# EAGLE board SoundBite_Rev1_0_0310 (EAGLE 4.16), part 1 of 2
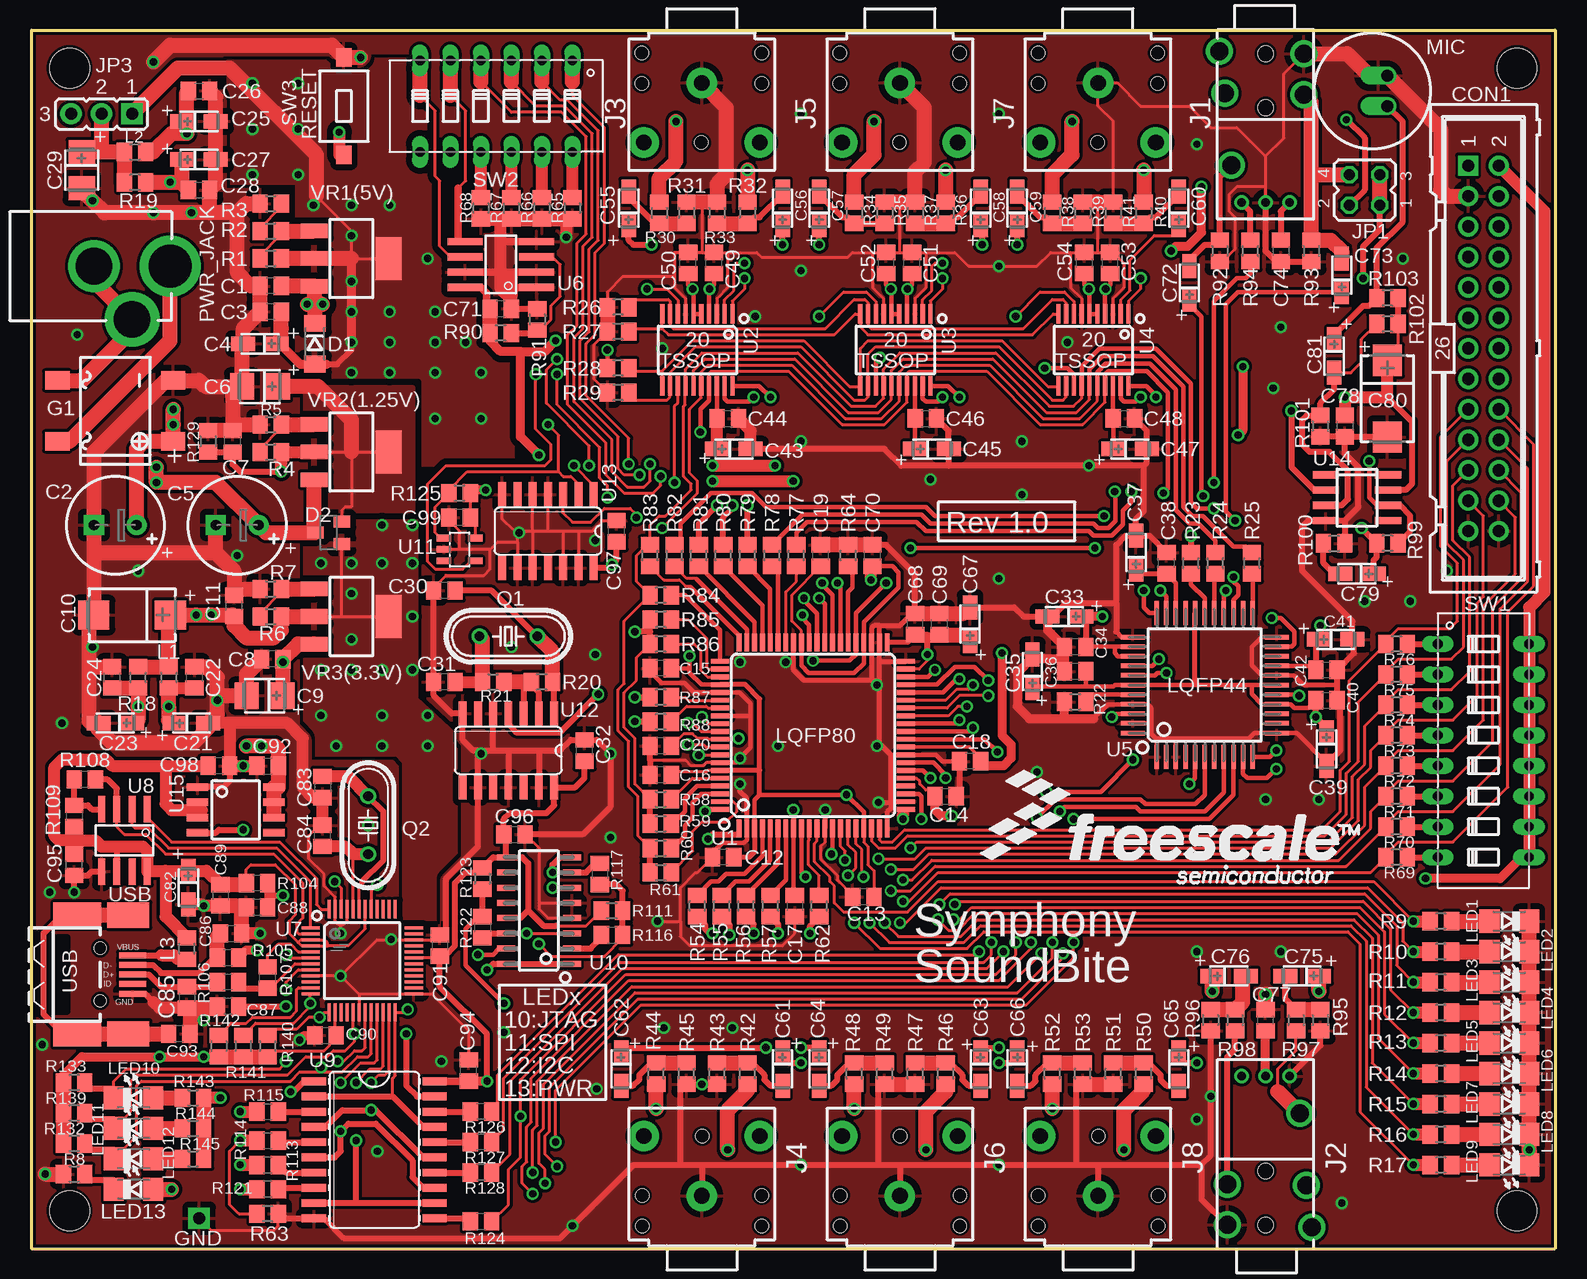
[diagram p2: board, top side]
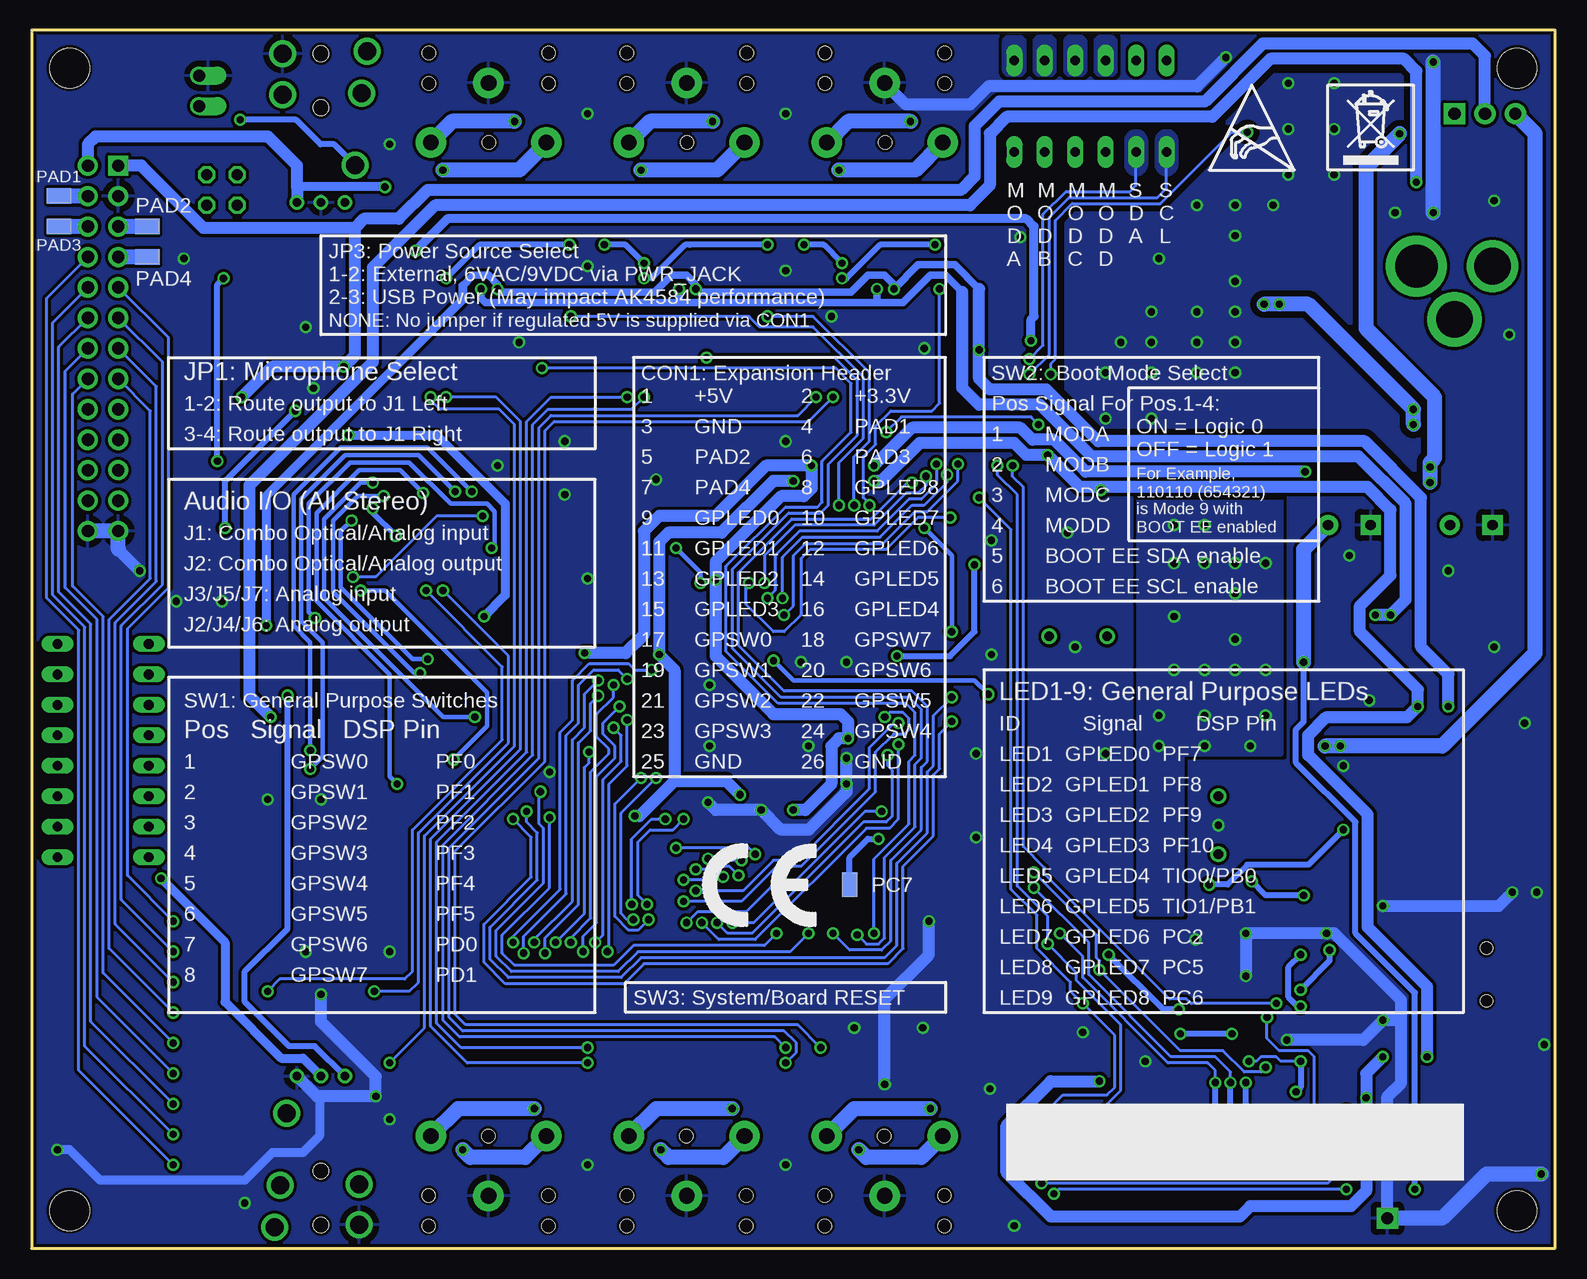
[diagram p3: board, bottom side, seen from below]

Size 127 x 101.6 mm. Coordinates in mm from the lower left corner, seen from the top.
Outline: 0,0 0,101.6 127,101.6 127,0 0,0
Copper layers (1*16): Top 0.035mm / dielectric 1.5mm / Bottom 0.035mm
Design rules "default": minimum track width 10mil, minimum drill 23.5mil, track to track 9.5mil, track to pad 9.5mil, pad to pad 9.5mil, via to via 9.5mil, smd to smd 0mil, copper to edge 10mil, drill to drill 8mil, minimum pad ring 10mil, minimum via ring 8mil, stop-mask expansion 4mil, vias tented up to drill 24mil, thermal gap 20mil
Net classes: 0 default: width 0.076 mm; 1 pwr: width 0.254 mm
Holes 3.3 mm at 3.17,98.42 123.83,98.42 123.83,3.17 3.17,3.17

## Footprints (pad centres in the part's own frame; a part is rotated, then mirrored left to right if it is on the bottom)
C0805_5MIL = smd 1.27 x 1.524: 1 -0.889,0; 2 0.889,0
E3,5-8 = drill 0.864 pad 1.676 round: + -1.778,0 | drill 0.864 pad 1.676 square: - 1.778,0
CT3216 = smd 2 x 1.2: + -1.4,0; - 1.4,0
CT3528 = smd 2 x 2.2: + -1.5,0; - 1.5,0
CT7343 = smd 2.6 x 2.4: + -3.2,0; - 3.2,0
0805 = smd 1.27 x 1.524: P$1 -0.889,0; P$2 0.889,0
ML26 = drill 1.016 pad 1.676 square: 1 -15.24,-1.27 | drill 1.016 pad 1.676 round: 2 -15.24,1.27; 3 -12.7,-1.27; 4 -12.7,1.27; 5 -10.16,-1.27; 6 -10.16,1.27; 7 -7.62,-1.27; 8 -7.62,1.27; 9 -5.08,-1.27; 10 -5.08,1.27; 11 -2.54,-1.27; 12 -2.54,1.27; 13 0,-1.27; 14 0,1.27; 15 2.54,-1.27; 16 2.54,1.27; 17 5.08,-1.27; 18 5.08,1.27; 19 7.62,-1.27; 20 7.62,1.27; 21 10.16,-1.27; 22 10.16,1.27; 23 12.7,-1.27; 24 12.7,1.27; 25 15.24,-1.27; 26 15.24,1.27
SOD80 = smd 1.4 x 1.8: 1 -1.7,0; 2 1.7,0
SOT23C = smd 1 x 1.4: 1 -0.95,-1.1; 2 0.95,-1.1; 3 0,1.1
DB104_SMD = smd 1.524 x 2.032: + -2.54,-4.826; - 2.54,-4.826; AC1 2.54,4.826; AC2 -2.54,4.826
TEST_PAD40/70/SQUARE = drill 1.016 pad 1.778 square: P$1 0,0
GP1FD210RP = drill 1.5 round: 1 3.2,4.5; 2 -2.85,-4.8; 3 3.2,1.1; 4 -3.4,1.2; 5 -3.85,4.7 | drill 0.7 round: 6 -2,-7.9; 7 0,-7.9; 8 2,-7.9 | hole 1.3: 0,4.5; 0,0
PHONE_JACK-TH = drill 1.3 pad 2.54 round: 1 4.945,-4.826; 2 -0.035,0; 3 4.945,4.826 | hole 1.1: 4.945,-0.034; -2.537,4.979; 0.003,4.979; -2.537,-5.002; 0.003,-5.002
JP2Q = drill 0.914 octagon: 1 -1.27,-1.27; 2 -1.27,1.27; 3 1.27,-1.27; 4 1.27,1.27
JP2 = drill 1.016 pad 1.778 square: 1 -2.54,0 | drill 1.016 pad 1.778 round: 2 0,0; 3 2.54,0
L0805 = smd 1.27 x 1.524: 1 -0.889,0; 2 0.889,0
SML-010 = smd 1.676 x 1.93: A 1.65,0; C -1.65,0
MIC = drill 1 offset: P+ -1.27,-1.27; P- 1.27,-1.27
SMD80/50 = smd 2.032 x 1.27: P$1 0,0
PWR_JACK_UNI = drill 3.556 pad 5.08 round: + -0.127,4.826 | drill 3.048 pad 4.318 round: - -6.477,4.826 | drill 3.048 pad 4.572 round: -- -3.302,0.381
HC49/S = drill 0.813 round: 1 -2.413,0; 2 2.413,0
HC49/S@2 = drill 0.813 round: 1 -2.413,0; 2 2.413,0
R0805_5MIL = smd 1.27 x 1.524: 1 -0.889,0; 2 0.889,0
DIP08YL = drill 0.813 long: 1 -8.89,-3.81; 2 -6.35,-3.81; 3 -3.81,-3.81; 4 -1.27,-3.81; 5 1.27,-3.81; 6 3.81,-3.81; 7 6.35,-3.81; 8 8.89,-3.81; 9 8.89,3.81; 10 6.35,3.81; 11 3.81,3.81; 12 1.27,3.81; 13 -1.27,3.81; 14 -3.81,3.81; 15 -6.35,3.81; 16 -8.89,3.81
DIP06YL = drill 0.813 long: 1 -6.35,-3.81; 2 -3.81,-3.81; 3 -1.27,-3.81; 4 1.27,-3.81; 5 3.81,-3.81; 6 6.35,-3.81; 7 6.35,3.81; 8 3.81,3.81; 9 1.27,3.81; 10 -1.27,3.81; 11 -3.81,3.81; 12 -6.35,3.81
SW-TAKT_6X3.5_SMD = smd 1.27 x 1.524: P$1 0,4.064; P$2 0,-4.064
LQFP80 = smd 0.4 x 1.5: 1 -6.175,-7.75; 2 -5.525,-7.75; 3 -4.875,-7.75; 4 -4.225,-7.75; 5 -3.575,-7.75; 6 -2.925,-7.75; 7 -2.275,-7.75; 8 -1.625,-7.75; 9 -0.975,-7.75; 10 -0.325,-7.75; 11 0.325,-7.75; 12 0.975,-7.75; 13 1.625,-7.75; 14 2.275,-7.75; 15 2.925,-7.75; 16 3.575,-7.75; 17 4.225,-7.75; 18 4.875,-7.75; 19 5.525,-7.75; 20 6.175,-7.75; 41 6.175,7.75; 42 5.525,7.75; 43 4.875,7.75; 44 4.225,7.75; 45 3.575,7.75; 46 2.925,7.75; 47 2.275,7.75; 48 1.625,7.75; 49 0.975,7.75; 50 0.325,7.75; 51 -0.325,7.75; 52 -0.975,7.75; 53 -1.625,7.75; 54 -2.275,7.75; 55 -2.925,7.75; 56 -3.575,7.75; 57 -4.225,7.75; 58 -4.875,7.75; 59 -5.525,7.75; 60 -6.175,7.75 | smd 1.5 x 0.4: 21 7.75,-6.175; 22 7.75,-5.525; 23 7.75,-4.875; 24 7.75,-4.225; 25 7.75,-3.575; 26 7.75,-2.925; 27 7.75,-2.275; 28 7.75,-1.625; 29 7.75,-0.975; 30 7.75,-0.325; 31 7.75,0.325; 32 7.75,0.975; 33 7.75,1.625; 34 7.75,2.275; 35 7.75,2.925; 36 7.75,3.575; 37 7.75,4.225; 38 7.75,4.875; 39 7.75,5.525; 40 7.75,6.175; 61 -7.75,6.175; 62 -7.75,5.525; 63 -7.75,4.875; 64 -7.75,4.225; 65 -7.75,3.575; 66 -7.75,2.925; 67 -7.75,2.275; 68 -7.75,1.625; 69 -7.75,0.975; 70 -7.75,0.325; 71 -7.75,-0.325; 72 -7.75,-0.975; 73 -7.75,-1.625; 74 -7.75,-2.275; 75 -7.75,-2.925; 76 -7.75,-3.575; 77 -7.75,-4.225; 78 -7.75,-4.875; 79 -7.75,-5.525; 80 -7.75,-6.175
TSSOP20 = smd 0.35 x 1.6: 1 -2.925,-3; 2 -2.275,-3; 3 -1.625,-3; 4 -0.975,-3; 5 -0.325,-3; 6 0.325,-3; 7 0.975,-3; 8 1.625,-3; 9 2.275,-3; 10 2.925,-3; 11 2.925,3; 12 2.275,3; 13 1.625,3; 14 0.975,3; 15 0.325,3; 16 -0.325,3; 17 -0.975,3; 18 -1.625,3; 19 -2.275,3; 20 -2.925,3
LQFP44 = smd 0.37 x 2: 1 -4,-6; 2 -3.2,-6; 3 -2.4,-6; 4 -1.6,-6; 5 -0.8,-6; 6 0,-6; 7 0.8,-6; 8 1.6,-6; 9 2.4,-6; 10 3.2,-6; 11 4,-6; 23 4,6; 24 3.2,6; 25 2.4,6; 26 1.6,6; 27 0.8,6; 28 0,6; 29 -0.8,6; 30 -1.6,6; 31 -2.4,6; 32 -3.2,6; 33 -4,6 | smd 2 x 0.37: 12 6,-4; 13 6,-3.2; 14 6,-2.4; 15 6,-1.6; 16 6,-0.8; 17 6,0; 18 6,0.8; 19 6,1.6; 20 6,2.4; 21 6,3.2; 22 6,4; 34 -6,4; 35 -6,3.2; 36 -6,2.4; 37 -6,1.6; 38 -6,0.8; 39 -6,0; 40 -6,-0.8; 41 -6,-1.6; 42 -6,-2.4; 43 -6,-3.2; 44 -6,-4
SO-08MN = smd 0.61 x 2.921: 1 -1.905,-2.981; 2 -0.635,-2.981; 3 0.635,-2.981; 4 1.905,-2.981; 5 1.905,2.981; 6 0.635,2.981; 7 -0.635,2.981; 8 -1.905,2.981
FT2232C_LQFP48 = smd 1.524 x 0.254: 1 -4.298,2.748; 2 -4.298,2.248; 3 -4.298,1.748; 4 -4.298,1.248; 5 -4.298,0.748; 6 -4.298,0.248; 7 -4.298,-0.252; 8 -4.298,-0.752; 9 -4.298,-1.252; 10 -4.298,-1.752; 11 -4.298,-2.252; 12 -4.298,-2.752; 25 4.302,-2.752; 26 4.302,-2.252; 27 4.302,-1.752; 28 4.302,-1.252; 29 4.302,-0.752; 30 4.302,-0.252; 31 4.302,0.248; 32 4.302,0.748; 33 4.302,1.248; 34 4.302,1.748; 35 4.302,2.248; 36 4.302,2.748 | smd 0.254 x 1.524: 13 -2.748,-4.302; 14 -2.248,-4.302; 15 -1.748,-4.302; 16 -1.248,-4.302; 17 -0.748,-4.302; 18 -0.248,-4.302; 19 0.252,-4.302; 20 0.752,-4.302; 21 1.252,-4.302; 22 1.752,-4.302; 23 2.252,-4.302; 24 2.752,-4.302; 37 2.752,4.298; 38 2.252,4.298; 39 1.752,4.298; 40 1.252,4.298; 41 0.752,4.298; 42 0.252,4.298; 43 -0.248,4.298; 44 -0.748,4.298; 45 -1.248,4.298; 46 -1.748,4.298; 47 -2.248,4.298; 48 -2.748,4.298
SO-08 = smd 0.6 x 2.2: 1 -1.905,-2.6; 2 -0.635,-2.6; 3 0.635,-2.6; 4 1.905,-2.6; 5 1.905,2.6; 6 0.635,2.6; 7 -0.635,2.6; 8 -1.905,2.6
SO20W = smd 0.66 x 2.032: 1 -5.715,-5.029; 2 -4.445,-5.029; 3 -3.175,-5.029; 4 -1.905,-5.029; 5 -0.635,-5.029; 6 0.635,-5.029; 7 1.905,-5.029; 8 3.175,-5.029; 9 4.445,-5.029; 10 5.715,-5.029; 11 5.715,5.029; 12 4.445,5.029; 13 3.175,5.029; 14 1.905,5.029; 15 0.635,5.029; 16 -0.635,5.029; 17 -1.905,5.029; 18 -3.175,5.029; 19 -4.445,5.029; 20 -5.715,5.029
SOIC16 = smd 0.5 x 1.5: 1 -4.445,-2.75; 2 -3.175,-2.75; 3 -1.905,-2.75; 4 -0.635,-2.75; 5 0.635,-2.75; 6 1.905,-2.75; 7 3.175,-2.75; 8 4.445,-2.75; 9 4.445,2.75; 10 3.175,2.75; 11 1.905,2.75; 12 0.635,2.75; 13 -0.635,2.75; 14 -1.905,2.75; 15 -3.175,2.75; 16 -4.445,2.75
SOT23-5 = smd 0.55 x 1.2: 1 -0.95,-1.3; 2 0,-1.3; 3 0.95,-1.3; 4 0.95,1.3; 5 -0.95,1.3
SO14 = smd 0.66 x 2.032: 1 -3.81,-3.073; 2 -2.54,-3.073; 3 -1.27,-3.073; 4 0,-3.073; 5 1.27,-3.073; 6 2.54,-3.073; 7 3.81,-3.073; 8 3.81,3.073; 9 2.54,3.073; 10 1.27,3.073; 11 0,3.073; 12 -1.27,3.073; 13 -2.54,3.073; 14 -3.81,3.073
SO08 = smd 0.6 x 2.2: 1 -1.905,-2.6; 2 -0.635,-2.6; 3 0.635,-2.6; 4 1.905,-2.6; 5 1.905,2.6; 6 0.635,2.6; 7 -0.635,2.6; 8 -1.905,2.6
R-PDSO-G8 = smd 0.635 x 1.778: 1 -1.905,-3.175; 2 -0.635,-3.175; 3 0.635,-3.175; 4 1.905,-3.175; 5 1.905,3.175; 6 0.635,3.175; 7 -0.635,3.175; 8 -1.905,3.175
USB_MINI_9PIN = smd 2.25 x 0.5: D+ 2.706,0; D- 2.706,0.8; GND 2.706,-1.6; ID 2.706,-0.8; VBUS 2.706,1.6 | smd 4 x 2.1: GND1 -1.9,4.95; GND3 -1.9,-4.95 | smd 3.5 x 2.1: GND2 2.35,4.95; GND4 2.35,-4.95 | hole 1: 0,2.2; 0,-2.2
SOT223 = smd 1.219 x 2.235: 1 -2.311,-3.099; 2 0,-3.099; 3 2.311,-3.099 | smd 3.6 x 2.2: 4 0,3.099

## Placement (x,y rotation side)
C1  100nF  [C0805_5MIL]  19.94,80.26 180 top
C2  220uF/16v/mini  [E3,5-8]  6.99,60.33 180 top
C3  100nF  [C0805_5MIL]  19.94,78.11 180 top
C4  10uF/6.3V  [CT3216]  19.05,75.44 180 top
C5  220uF/16V/mini  [E3,5-8]  17.14,60.33 180 top
C6  47uF/6.3V  [CT3528]  19.05,71.88 180 top
C7  100nF  [C0805_5MIL]  16.76,67.31 90 top
C8  100nF  [C0805_5MIL]  20.07,49.15 180 top
C9  10uF/16V  [CT3528]  19.43,46.1 180 top
C10  100uF/6.3V  [CT7343]  8.38,52.83 180 top
C11  100nF  [C0805_5MIL]  16.89,53.59 90 top
C12  100nF  [C0805_5MIL]  57.66,32.64 180 top
C13  100nF  [C0805_5MIL]  69.34,29.34 180 top
C14  100nF  [C0805_5MIL]  76.2,37.72 0 top
C15  100nF  [C0805_5MIL]  52.45,48.39 180 top
C16  100nF  [C0805_5MIL]  52.45,39.5 180 top
C17  100nF  [C0805_5MIL]  63.63,28.57 270 top
C18  100nF  [C0805_5MIL]  78.23,40.64 180 top
C19  100nF  [C0805_5MIL]  65.79,57.78 90 top
C20  100nF  [C0805_5MIL]  52.45,41.91 180 top
C21  10uF/6.3V  [CT3216]  13.34,43.81 0 top
C22  100nF  [C0805_5MIL]  13.59,47.62 90 top
C23  10uF/6.3V  [CT3216]  6.99,43.81 180 top
C24  100nF  [C0805_5MIL]  6.73,47.62 90 top
C25  10uF/6.3V  [CT3216]  13.97,93.98 0 top
C26  100nF  [C0805_5MIL]  13.97,96.52 0 top
C27  10uF/6.3V  [CT3216]  13.97,90.81 0 top
C28  100nF  [C0805_5MIL]  13.97,88.27 0 top
C29  47uF/6.3V  [CT3528]  4.19,89.92 270 top
C30  22pF  [C0805_5MIL]  34.42,54.86 180 top
C31  22pF  [C0805_5MIL]  34.42,47.24 180 top
C32  100nF  [C0805_5MIL]  46.1,41.53 90 top
C33  10uF/6.3V  [CT3216]  86.11,52.7 180 top
C34  100nF  [C0805_5MIL]  87,50.16 180 top
C35  10uF/6.3V  [CT3216]  83.44,48.13 90 top
C36  100nF  [C0805_5MIL]  87,48.13 180 top
C37  4.7uF/6.3V  [CT3216]  92.08,58.04 90 top
C38  100nF  [C0805_5MIL]  94.61,57.15 90 top
C39  10uF/6.3V  [CT3216]  107.95,41.66 270 top
C40  100nF  [C0805_5MIL]  107.95,45.72 0 top
C41  10uF/6.3V  [CT3216]  108.71,50.8 0 top
C42  100nF  [C0805_5MIL]  107.95,48.26 0 top
C43  4.7uF/6.3V  [CT3216]  58.55,66.67 0 top
C44  100nF  [C0805_5MIL]  58.04,69.22 0 top
C45  4.7uF/6.3V  [CT3216]  75.06,66.67 0 top
C46  100nF  [C0805_5MIL]  74.55,69.22 0 top
C47  4.7uF/6.3V  [CT3216]  91.57,66.67 0 top
C48  100nF  [C0805_5MIL]  91.06,69.22 0 top
C49  100nF  [C0805_5MIL]  56.9,82.17 90 top
C50  100nF  [C0805_5MIL]  54.74,82.17 90 top
C51  100nF  [C0805_5MIL]  73.41,82.17 90 top
C52  100nF  [C0805_5MIL]  71.25,82.17 90 top
C53  100nF  [C0805_5MIL]  89.92,82.17 90 top
C54  100nF  [C0805_5MIL]  87.76,82.17 90 top
C55  10uF/6.3V  [CT3216]  49.78,86.74 90 top
C56  10uF/6.3V  [CT3216]  62.61,86.74 90 top
C57  10uF/6.3V  [CT3216]  65.66,86.74 90 top
C58  10uF/6.3V  [CT3216]  79.12,86.74 90 top
C59  10uF/6.3V  [CT3216]  82.17,86.74 90 top
C60  10uF/6.3V  [CT3216]  95.63,86.74 90 top
C61  22uF/6.3V  [CT3216]  62.61,14.99 270 top
C62  22uF/6.3V  [CT3216]  49.15,14.99 270 top
C63  22uF/6.3V  [CT3216]  79.12,14.99 270 top
C64  22uF/6.3V  [CT3216]  65.66,14.99 270 top
C65  22uF/6.3V  [CT3216]  95.63,14.99 270 top
C66  22uF/6.3V  [CT3216]  82.17,14.99 270 top
C67  10uF/6.3V  [CT3216]  78.23,52.07 90 top
C68  100nF  [C0805_5MIL]  73.66,52.07 90 top
C69  100nF  [C0805_5MIL]  75.69,52.07 90 top
C70  100nF  [C0805_5MIL]  70.1,57.78 90 top
C71  100nF  [C0805_5MIL]  39.12,78.36 0 top
C72  10uF/6.3V  [CT3216]  96.52,80.52 90 top
C73  10uF/6.3V  [CT3216]  109.22,81.15 90 top
C74  100nF  [C0805_5MIL]  104.14,83.19 270 top
C75  22uF/6.3V  [CT3216]  105.92,22.73 180 top
C76  22uF/6.3V  [CT3216]  99.82,22.73 0 top
C77  100nF  [C0805_5MIL]  102.87,19.05 90 top
C78  100nF  [C0805_5MIL]  109.47,68.58 270 top
C79  10uF/6.3V  [CT3216]  110.49,56.26 180 top
C80  100uF/6.3V  [CT7343]  113.03,70.87 270 top
C81  10uF/6.3V  [CT3216]  108.58,74.42 270 top
C82  10u/6.3V  [CT3216]  13.08,30.1 270 top
C83  27pF  [0805]  24.26,38.48 270 top
C84  27pF  [0805]  24.26,34.42 90 top
C85  47pF  [0805]  12.95,20.95 270 top
C86  47pF  [0805]  16.64,26.29 0 top
C87  100nF  [0805]  16.38,20.19 180 top
C88  100nF  [0805]  18.8,28.45 180 top
C89  100nF  [0805]  15.75,29.46 270 top
C90  100nF  [0805]  24.51,17.78 0 top
C91  100nF  [0805]  34.04,25.27 270 top
C92  100n  [0805]  19.68,40.26 0 top
C93  10nF  [C0805_5MIL]  12.32,17.91 180 top
C94  100n  [0805]  36.45,14.86 90 top
C95  100nF  [0805]  3.56,32 90 top
C96  100n  [0805]  40.26,34.54 0 top
C97  100nF  [C0805_5MIL]  48.77,59.82 90 top
C98  100n  [0805]  15.62,40.26 180 top
C99  100nF  [C0805_5MIL]  35.69,60.96 180 top
CON1  [ML26]  121.03,75.06 270 top
D1  1N4148  [SOD80]  23.62,75.44 270 top
D2  BAT54  [SOT23C]  24.77,59.69 90 top
G1  DB104(SMD)  [DB104_SMD]  6.99,69.85 90 top
GND  TESTPAD3  [TEST_PAD40/70/SQUARE]  13.97,2.54 0 top
J1  DLR13M12  [GP1FD210RP]  102.87,95.12 0 top
J2  DLT13M12  [GP1FD210RP]  102.87,6.48 180 top
J3  JACK-3PINPHONE_JACK-TH  [PHONE_JACK-TH]  55.88,97.16 270 top
J4  JACK-3PINPHONE_JACK-TH  [PHONE_JACK-TH]  55.88,4.45 90 top
J5  JACK-3PINPHONE_JACK-TH  [PHONE_JACK-TH]  72.39,97.16 270 top
J6  JACK-3PINPHONE_JACK-TH  [PHONE_JACK-TH]  72.39,4.45 90 top
J7  JACK-3PINPHONE_JACK-TH  [PHONE_JACK-TH]  88.9,97.16 270 top
J8  JACK-3PINPHONE_JACK-TH  [PHONE_JACK-TH]  88.9,4.45 90 top
JP1  [JP2Q]  111.12,88.27 90 top
JP3  [JP2]  5.84,94.61 180 top
L1  FERRITE BEAD  [L0805]  11.43,47.62 270 top
L2  FERRITE BEAD  [L0805]  8.64,91.44 0 top
L3  FERRITE BEAD  [L0805]  12.95,25.02 90 top
LED1  green  [SML-010]  123.19,27.3 180 top
LED2  green  [SML-010]  123.19,24.77 180 top
LED3  green  [SML-010]  123.19,22.23 180 top
LED4  green  [SML-010]  123.19,19.68 180 top
LED5  yellow  [SML-010]  123.19,17.14 180 top
LED6  yellow  [SML-010]  123.19,14.61 180 top
LED7  red  [SML-010]  123.19,12.06 180 top
LED8  red  [SML-010]  123.19,9.53 180 top
LED9  red  [SML-010]  123.19,6.99 180 top
LED10  yellow  [SML-010]  8.51,12.57 0 top
LED11  yellow  [SML-010]  8.51,10.03 0 top
LED12  yellow  [SML-010]  8.51,7.49 0 top
LED13  green  [SML-010]  8.51,4.95 0 top
MIC  [MIC]  111.76,96.52 90 top
PAD1  TESTPAD80/50  [SMD80/50]  124.71,87.76 0 bottom
PAD2  TESTPAD80/50  [SMD80/50]  117.35,85.22 0 bottom
PAD3  TESTPAD80/50  [SMD80/50]  124.71,85.22 0 bottom
PAD4  TESTPAD80/50  [SMD80/50]  117.35,82.68 0 bottom
PC7  TESTPAD80/50  [SMD80/50]  58.8,30.35 270 bottom
PWR_JACK  [PWR_JACK_UNI]  11.68,77.09 0 top
Q1  24.576MHz  [HC49/S]  39.75,51.05 180 top
Q2  6MHz  [HC49/S@2]  28.07,35.31 90 top
R1  220/1%  [R0805_5MIL]  19.94,82.55 0 top
R2  330/1%  [R0805_5MIL]  19.94,84.84 0 top
R3  330/1%  [R0805_5MIL]  19.94,87.12 0 top
R4  NA  [R0805_5MIL]  19.94,66.42 0 top
R5  0  [R0805_5MIL]  19.94,68.71 0 top
R6  240/1%  [R0805_5MIL]  19.94,52.7 0 top
R7  390/1%  [R0805_5MIL]  19.94,54.99 0 top
R8  560  [R0805_5MIL]  3.56,6.22 0 top
R9  270  [R0805_5MIL]  117.47,27.3 180 top
R10  270  [R0805_5MIL]  117.47,24.77 180 top
R11  270  [R0805_5MIL]  117.47,22.23 180 top
R12  270  [R0805_5MIL]  117.47,19.68 180 top
R13  270  [R0805_5MIL]  117.47,17.14 180 top
R14  270  [R0805_5MIL]  117.47,14.61 180 top
R15  270  [R0805_5MIL]  117.47,12.06 180 top
R16  270  [R0805_5MIL]  117.47,9.53 180 top
R17  270  [R0805_5MIL]  117.47,6.99 180 top
R18  10  [R0805_5MIL]  8.89,47.62 90 top
R19  5.1  [R0805_5MIL]  8.64,88.9 180 top
R20  100k  [R0805_5MIL]  42.55,47.24 180 top
R21  1k  [R0805_5MIL]  38.48,47.24 0 top
R22  13k/1%  [R0805_5MIL]  87,45.59 0 top
R23  100  [R0805_5MIL]  96.65,57.15 90 top
R24  100  [R0805_5MIL]  98.68,57.15 90 top
R25  100  [R0805_5MIL]  101.73,57.15 90 top
R26  4.7k  [R0805_5MIL]  48.9,78.49 180 top
R27  4.7k  [R0805_5MIL]  48.9,76.45 180 top
R28  4.7k  [R0805_5MIL]  48.9,73.41 180 top
R29  4.7k  [R0805_5MIL]  48.9,71.37 180 top
R30  0  [R0805_5MIL]  52.32,86.36 270 top
R31  10k  [R0805_5MIL]  54.61,86.36 270 top
R32  0  [R0805_5MIL]  59.69,86.36 270 top
R33  10k  [R0805_5MIL]  57.15,86.36 270 top
R34  0  [R0805_5MIL]  68.58,86.36 270 top
R35  10k  [R0805_5MIL]  71.12,86.36 270 top
R36  0  [R0805_5MIL]  76.2,86.36 270 top
R37  10k  [R0805_5MIL]  73.66,86.36 270 top
R38  0  [R0805_5MIL]  85.09,86.36 270 top
R39  10k  [R0805_5MIL]  87.63,86.36 270 top
R40  0  [R0805_5MIL]  92.71,86.36 270 top
R41  10k  [R0805_5MIL]  90.17,86.36 270 top
R42  220  [R0805_5MIL]  59.69,14.61 90 top
R43  10k  [R0805_5MIL]  57.15,14.61 90 top
R44  220  [R0805_5MIL]  52.07,14.61 90 top
R45  10k  [R0805_5MIL]  54.61,14.61 90 top
R46  220  [R0805_5MIL]  76.2,14.61 90 top
R47  10k  [R0805_5MIL]  73.66,14.61 90 top
R48  220  [R0805_5MIL]  68.58,14.61 90 top
R49  10k  [R0805_5MIL]  71.12,14.61 90 top
R50  220  [R0805_5MIL]  92.71,14.61 90 top
R51  10k  [R0805_5MIL]  90.17,14.61 90 top
R52  220  [R0805_5MIL]  85.09,14.61 90 top
R53  10k  [R0805_5MIL]  87.63,14.61 90 top
R54  100  [R0805_5MIL]  55.5,28.57 90 top
R55  100  [R0805_5MIL]  57.53,28.57 90 top
R56  100  [R0805_5MIL]  59.56,28.57 90 top
R57  100  [R0805_5MIL]  61.59,28.57 90 top
R58  0  [R0805_5MIL]  52.45,37.47 0 top
R59  0  [R0805_5MIL]  52.45,35.43 0 top
R60  0  [R0805_5MIL]  52.45,33.4 0 top
R61  0  [R0805_5MIL]  52.45,31.37 0 top
R62  0  [R0805_5MIL]  65.66,28.57 90 top
R63  4.7k  [R0805_5MIL]  19.68,2.92 180 top
R64  0  [R0805_5MIL]  68.07,57.78 90 top
R65  4.7k  [R0805_5MIL]  45.09,86.74 270 top
R66  4.7k  [R0805_5MIL]  42.55,86.74 270 top
R67  4.7k  [R0805_5MIL]  40.01,86.74 270 top
R68  4.7k  [R0805_5MIL]  37.47,86.74 270 top
R69  4.7k  [R0805_5MIL]  113.79,32.64 180 top
R70  4.7k  [R0805_5MIL]  113.79,35.18 180 top
R71  4.7k  [R0805_5MIL]  113.79,37.72 180 top
R72  4.7k  [R0805_5MIL]  113.79,40.26 180 top
R73  4.7k  [R0805_5MIL]  113.79,42.8 180 top
R74  4.7k  [R0805_5MIL]  113.79,45.34 180 top
R75  4.7k  [R0805_5MIL]  113.79,47.88 180 top
R76  4.7k  [R0805_5MIL]  113.79,50.42 180 top
R77  0  [R0805_5MIL]  63.75,57.78 90 top
R78  0  [R0805_5MIL]  61.72,57.78 90 top
R79  100  [R0805_5MIL]  59.69,57.78 90 top
R80  100  [R0805_5MIL]  57.66,57.78 90 top
R81  100  [R0805_5MIL]  55.63,57.78 90 top
R82  100  [R0805_5MIL]  53.59,57.78 90 top
R83  0  [R0805_5MIL]  51.56,57.78 90 top
R84  0  [R0805_5MIL]  52.45,54.48 180 top
R85  0  [R0805_5MIL]  52.45,52.45 180 top
R86  0  [R0805_5MIL]  52.45,50.42 180 top
R87  0  [R0805_5MIL]  52.45,45.97 180 top
R88  0  [R0805_5MIL]  52.45,43.94 180 top
R90  NA  [R0805_5MIL]  39.12,76.33 180 top
R91  0  [R0805_5MIL]  42.16,77.47 270 top
R92  10k  [R0805_5MIL]  99.06,83.19 270 top
R93  10k  [R0805_5MIL]  106.68,83.19 270 top
R94  470  [R0805_5MIL]  101.6,83.19 90 top
R95  10k  [R0805_5MIL]  107.44,19.05 270 top
R96  10k  [R0805_5MIL]  98.3,19.05 270 top
R97  220  [R0805_5MIL]  105.41,19.05 270 top
R98  220  [R0805_5MIL]  100.33,19.05 270 top
R99  22k  [R0805_5MIL]  113.03,58.8 180 top
R100  1k  [R0805_5MIL]  108.58,58.8 0 top
R101  47k  [R0805_5MIL]  107.44,68.58 270 top
R102  47k  [R0805_5MIL]  113.03,77.09 180 top
R103  4.7k  [R0805_5MIL]  113.03,79.25 180 top
R104  470  [0805]  18.8,30.48 180 top
R105  27  [0805]  16.38,24.26 180 top
R106  27  [0805]  16.38,22.23 180 top
R107  1.5k  [0805]  19.68,22.61 90 top
R108  2.2k  [0805]  4.45,39.12 180 top
R109  10k  [0805]  3.56,36.07 270 top
R111  10k  [R0805_5MIL]  48.39,28.19 0 top
R113  0  [0805]  19.68,6.99 0 top
R114  0  [0805]  19.68,9.02 0 top
R115  0  [0805]  19.68,11.43 0 top
R116  0  [0805]  48.39,26.16 0 top
R117  0  [0805]  47.37,31.24 270 top
R121  0  [0805]  19.68,4.95 180 top
R122  0  [0805]  37.59,26.8 270 top
R123  10k  [R0805_5MIL]  37.59,30.86 270 top
R124  0  [0805]  37.47,2.29 0 top
R125  10K  [R0805_5MIL]  35.69,62.99 0 top
R126  0  [0805]  37.47,11.43 180 top
R127  0  [0805]  37.47,8.89 180 top
R128  0  [0805]  37.47,6.35 180 top
R129  1k  [R0805_5MIL]  14.73,67.31 270 top
R132  4.7k  [R0805_5MIL]  3.56,8.76 180 top
R133  4.7k  [R0805_5MIL]  3.56,13.84 180 top
R139  4.7k  [R0805_5MIL]  3.56,11.3 180 top
R140  4.7k  [R0805_5MIL]  19.68,16.89 270 top
R141  4.7k  [R0805_5MIL]  17.65,16.89 270 top
R142  4.7k  [R0805_5MIL]  15.62,16.89 270 top
R143  270  [R0805_5MIL]  13.46,12.57 0 top
R144  270  [R0805_5MIL]  13.46,10.03 0 top
R145  270  [R0805_5MIL]  13.46,7.49 0 top
SW1  [DIP08YL]  121.03,41.53 270 top
SW2  [DIP06YL]  38.73,95.25 180 top
SW3  RESET  [SW-TAKT_6X3.5_SMD]  26.04,95.25 180 top
U1  DSP56371LQFP80  [LQFP80]  65.15,42.8 0 top
U2  AK4556TSSOP20  [TSSOP20]  55.5,74.93 180 top
U3  AK4556TSSOP20  [TSSOP20]  72.01,74.93 180 top
U4  AK4556TSSOP20  [TSSOP20]  88.52,74.93 180 top
U5  AK4584LQFP44  [LQFP44]  97.79,46.99 0 top
U6  24LC256  [SO-08MN]  39.12,82.04 90 top
U7  FT2232C  [FT2232C_LQFP48]  27.56,24 0 top
U8  93LC46SN  [SO-08]  7.75,34.04 180 top
U9  74AC244DW  [SO20W]  28.57,8.26 270 top
U10  ISL43140IBSOIC16  [SOIC16]  42.29,28.19 90 top
U11  MCP1322  [SOT23-5]  35.69,58.29 270 top
U12  74AC04D  [SO14]  39.75,41.53 180 top
U13  74AC08D  [SO14]  43.05,59.82 180 top
U14  MCP601  [SO08]  110.49,62.61 270 top
U15  TPS2021  [R-PDSO-G8]  17.02,36.58 270 top
U$1  [FREESCALE_LOGO]  80.01,32.38 0 top
U$2  [CE]  71.12,26.8 0 bottom
U$3  [ESD_SYMBOL]  28.83,89.92 0 bottom
U$4  [RECYCLE_BIN1/8]  17.65,90.36 0 bottom
USB  MINI_USB  [USB_MINI_9PIN]  5.71,22.86 0 top
VR1(5V)  LD1117ASTR  [SOT223]  26.67,82.55 270 top
VR2(1.25V)  LD1117ASTR  [SOT223]  26.67,66.42 270 top
VR3(3.3V)  LD1117ASTR  [SOT223]  26.67,52.7 270 top

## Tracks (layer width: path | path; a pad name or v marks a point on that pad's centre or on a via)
+5V  (via drill 0.6)
  Top 0.254: D2.3 23.62,59.69 23.57,59.74 | 12.95,93.98 C25.+ | 23.55,50.42 VR3(3.3V).3
  Top 1.27: 23.62,59.69 19.56,59.69 C5.+ 15.37,63.88 v10.41,63.88 v10.41,65.15 | 23.57,59.74 VR2(1.25V).3 | C26.1 12.95,96.39 12.95,93.98 v12.95,92.96 11.68,92.96 10.16,91.44 L2.2 | 23.55,50.42 22.23,50.42 C8.1 v20.95,48.9 20.95,46.08 | LED13.A v11.68,4.95 | 20.95,46.08 20.95,45.97 | 20.95,46.08 C9.+
  Bottom 0.508: v11.68,4.95 11.68,21.34 16.64,26.29 16.64,35.56 21.59,40.51 21.59,43.31 20.95,43.94 v20.95,48.9
  Bottom 1.27: v20.95,48.9 20.95,58.29 C5.+ | v10.41,63.88 v10.41,65.15 10.41,65.53 10.03,65.91 10.03,70.99 15.75,76.71 15.75,90.17 v12.95,92.96
+5V_EXT  (via drill 0.6)
  Top 0.254: C4.+ 20.7,75.44 | 29.84,82.55 VR1(5V).4 26.67,82.55 v26.67,84.45 26.67,84.84 23.75,87.76
  Top 0.508: 24.59,73.74 25.48,73.74 26.67,74.93 26.67,75.82
  Top 0.762: 20.7,75.44 22.4,73.74 D1.2 24.59,73.74 | 26.67,75.82 v26.67,80.64 26.67,82.55
  Top 1.27: R1.2 VR1(5V).2 26.67,82.55 | C4.+ 20.83,75.44 20.83,76.71 | 20.83,76.71 | 20.83,76.71 C3.1 | JP3.1 12.19,98.42 16.51,98.42 23.75,91.19 23.75,87.76
  other vias: 26.67,87 29.84,87 33.02,82.55 33.66,78.11 29.84,78.11 26.67,78.11 26.67,73.03 29.84,73.03 33.66,73.03 37.47,73.03 37.47,69.22 33.66,69.22 36.2,75.56 33.66,75.56 29.84,75.56 26.67,75.56 23.5,87 22.23,89.53 18.41,89.53 18.41,93.34 22.23,93.34 18.41,97.16 22.23,97.16
  pour Top (isolate 0.508, rank 3): 40.01,65.41 22.23,65.41 22.23,88.9 16.51,88.9 16.51,99.06 32.38,99.06 34.29,97.16 34.29,85.72 40.01,85.72
  pour Bottom (isolate 0.508, rank 3): 12.7,97.79 12.7,93.34 15.88,90.17 15.88,75.56 10.79,70.48 10.79,62.87 15.88,67.94 38.73,67.94 40.64,69.85 40.64,88.9 32.38,88.9 23.5,97.79
  pour Top (isolate 0.508, rank 2, no thermals): 27.94,85.09 31.75,85.09 31.75,80.01 27.94,80.01
AK4584_CCLK  (via drill 0.6)
  Top 0.381: U5.10 100.99,39.6 101.35,39.24 103,39.24 v103.76,40.01 | v91.69,63.12 91.69,62.23 91,61.53 91,60.39 90.04,59.44 88.52,59.44 88.14,59.82 74.55,59.82 73.79,60.58 64.64,60.58 63.75,59.69 R77.2
  Bottom 0.381: v103.76,40.01 102.74,41.02 102.74,50.55 104.52,52.32 104.52,62.48 100.84,66.17 94.74,66.17 v91.69,63.12
AK4584_CDTI  (via drill 0.6)
  Top 0.381: v85.72,36.45 86.11,36.83 92.08,36.83 92.46,36.45 97.79,36.45 99.39,38.05 U5.8
  Top 0.508: v50.29,45.97 R87.2
  Bottom 0.254: v50.29,45.97 51.82,44.45 51.82,40.26 52.32,39.75 52.32,34.67 54.86,32.13 54.86,25.27 55.88,24.26 76.2,24.26 77.85,22.61 87.25,22.61 88.77,24.13 88.77,26.8 84.84,30.73 84.84,34.67 85.72,35.56 v85.72,36.45
AK4584_CDTO  (via drill 0.6)
  Top 0.381: U5.9 100.19,37.83 98.17,35.81 v86.87,35.81
  Top 0.508: v50.29,43.94 R88.2
  Bottom 0.254: v50.29,43.94 51.31,42.93 51.31,40.01 51.82,39.5 51.82,34.42 54.36,31.88 54.36,25.02 55.63,23.75 75.95,23.75 77.6,22.1 87.5,22.1 89.28,23.88 89.28,27.05 85.34,30.99 85.34,34.29 v86.87,35.81
AK4584_CSN  (via drill 0.6)
  Top 0.381: U5.11 103.22,40.99 v103.76,41.53 | v90.3,63.12 90.3,62.87 90.36,62.8 90.36,60.64 89.79,60.07 88.9,60.07 88.52,60.45 74.93,60.45 74.17,61.21 64.26,61.21 R78.2
  Bottom 0.381: v103.76,41.53 103.76,50.55 105.16,51.94 105.16,62.87 101.22,66.8 93.98,66.8 v90.3,63.12
AK4584_INT0  (via drill 0.6)
  Top 0.381: U5.6 97.79,37.85 97.03,37.08 92.84,37.08 92.46,37.47 85.34,37.47 v83.82,35.94
  Top 0.508: R62.1 64.9,26.92 v64.9,26.29
  Bottom 0.254: v64.9,26.29 65.91,25.27 76.83,25.27 78.49,23.62 86.74,23.62 87.76,24.64 87.76,26.16 83.82,30.1 v83.82,35.94
CKS0
  Top 0.254: U4.9 86.24,78.86 85.98,79.12 85.09,79.12 82.68,76.71 69.98,76.71 69.73,76.95 U3.9 69.73,78.86 69.47,79.12 68.58,79.12 66.17,76.71 53.47,76.71 53.22,76.95 U2.9 53.22,78.98 53.09,79.12 50.42,79.12 R26.1
CKS1
  Top 0.254: 52.57,76.71 U2.10 | 52.57,76.71 53.09,76.2 66.93,76.2 68.66,77.93 U3.10 69.08,76.84 69.72,76.2 83.44,76.2 85.17,77.93 U4.10 | 52.57,76.71 50.04,76.71 R27.1
CKS2
  Top 0.254: 52.57,73.15 U2.11 | U4.11 85.6,71.88 84.71,71.88 80.9,75.69 69.72,75.69 69.08,75.05 U3.11 69.09,71.88 68.2,71.88 64.39,75.69 55.12,75.69 52.57,73.15 | 52.57,73.15 50.04,73.15 R28.1
CKS3
  Top 0.254: U4.12 86.24,71 85.98,70.74 85.09,70.74 80.64,75.18 70.36,75.18 69.73,74.56 U3.12 69.73,71 69.47,70.74 68.58,70.74 64.14,75.18 55.37,75.18 53.22,73.04 U2.12 53.22,71 52.96,70.74 50.42,70.74 R29.1
COD0_STDI  (via drill 0.6)
  Top 0.381: U5.26 99.39,54.69 v99.57,54.86 | v84.58,38.1 89.15,38.1 v91.82,40.77
  Top 0.508: v62.23,26.29 62.23,27.05 R57.1
  Bottom 0.254: v62.23,26.29 63.75,24.77 76.45,24.77 78.11,23.11 87,23.11 88.27,24.38 88.27,26.54 84.33,30.48 84.33,35.05 84.71,35.43 84.71,38.1 v84.58,38.1
  Bottom 0.381: v91.82,40.77 89.03,43.56 89.03,46.35 97.54,54.86 v99.57,54.86
COD0_STDO  (via drill 0.6)
  Top 0.381: U5.25 100.19,54.09 100.58,54.48 100.58,55.24 100.2,55.63 v100.2,56.01 | 54.1,59.18 54.1,60.45 56.64,62.99 60.07,62.99 61.21,61.85 74.55,61.85 75.31,61.09 v89.41,61.09
  Top 0.508: R82.2 54.1,59.18
  Bottom 0.254: v100.2,56.01 98.3,56.01 93.22,61.09 v89.41,61.09
COD1_STDI  (via drill 0.6)
  Top 0.254: U2.13 53.87,70.51 53.59,70.23 v53.59,63.88
  Top 0.508: v60.2,26.29 60.2,27.05 R56.1
  Bottom 0.254: v60.2,26.29 58.8,24.89 56.13,24.89 55.37,25.65 55.37,32.38 52.83,34.92 52.83,40.13 52.32,40.64 52.32,45.21 53.59,46.48 64.26,46.48 68.07,50.29 68.07,56.39 63.63,60.83 57.02,60.83 53.98,63.88 v53.59,63.88
COD1_STDO  (via drill 0.6)
  Top 0.254: U2.8 53.87,79.09 52.96,80.01 v51.31,80.01
  Top 0.508: R81.2 55.63,60.45 v57.15,61.98
  Bottom 0.254: v51.31,80.01 51.31,70.48 51.94,69.85 55.37,69.85 56.64,68.58 56.64,67.06 57.66,66.04 57.66,62.61 57.15,62.1 v57.15,61.98
COD2_STDI  (via drill 0.6)
  Top 0.356: U3.13 70.38,73.94 v70.74,74.3
  Top 0.508: v58.17,26.16 58.17,27.05 R55.1
  Bottom 0.254: v70.74,74.3 60.07,74.3 58.17,72.39 58.17,67.82 60.58,65.41 60.58,61.98 61.21,61.34 63.88,61.34 68.58,56.64 68.58,50.04 64.52,45.97 53.85,45.97 52.83,44.96 52.83,40.89 53.34,40.39 53.34,35.18 55.88,32.64 55.88,25.91 56.39,25.4 57.4,25.4 v58.17,26.16
COD2_STDO  (via drill 0.6)
  Top 0.254: U3.8 70.38,78.97 69.6,79.76 67.69,79.76 v65.66,77.72
  Top 0.508: R80.2 57.66,60.96 58.42,61.72 v58.42,61.98
  Bottom 0.254: v65.66,77.72 61.85,77.72 57.15,73.03 57.15,67.31 58.42,66.04 v58.42,61.98
COD3_STDI  (via drill 0.6)
  Top 0.356: U4.13 86.89,72.87 86.36,73.41 v84.45,73.41
  Top 0.508: v56.77,26.29 56.52,26.29 56.13,26.67 56.13,27.05 R54.1
  Bottom 0.254: v84.45,73.41 59.94,73.41 58.67,72.14 58.67,68.07 61.09,65.66 61.09,62.23 61.47,61.85 64.14,61.85 69.09,56.9 69.09,49.78 64.77,45.47 54.1,45.47 53.34,44.7 53.34,41.15 53.85,40.64 53.85,35.43 56.77,32.51 v56.77,26.29
COD3_STDO  (via drill 0.6)
  Top 0.254: U4.8 86.89,78.97 86.11,79.76 84.07,79.76 v82.04,77.72
  Top 0.508: R79.2 v59.69,61.98
  Bottom 0.254: v82.04,77.72 67.18,77.72 66.29,76.83 61.85,76.83 57.66,72.64 57.66,67.56 59.69,65.53 v59.69,61.98
DSP_RESET  (via drill 0.6)
  Top 0.254: U13.3 44.32,61.34 45.09,60.58 46.61,60.58 47.75,61.72 49.91,61.72 50.42,61.21 v50.42,60.96
  Top 0.381: U1.47 67.43,55.26 v67.18,55.5
  Bottom 0.254: v67.18,55.5 67.44,55.24 67.44,53.72 65.15,51.44 64.26,51.44 62.87,52.83 62.87,57.53 62.1,58.29 55.75,58.29 53.09,60.96 v50.42,60.96
EE_SCL
  Top 0.254: U6.6 34.92,82.68 34.04,83.57 34.04,89.03 33.66,89.41 33.66,94.87 32.38,96.14
  Top 1.27: 32.38,96.14 SW2.6
EE_SDA
  Top 0.254: 35.56,88.39 36.2,89.03 36.2,94.87 34.92,96.14
  Top 0.61: U6.5 35.56,83.95 35.56,88.39
  Top 1.27: 34.92,96.14 SW2.5
GND  (via drill 0.6)
  Top 0.254: LED2.C | LED3.C | LED4.C | LED5.C | LED6.C | LED7.C | LED8.C | LED9.C | C89.P$2 | 17.27,28.45 17.14,28.57 | C4.- 17.55,75.33 | 25.78,27.05 25.53,27.05 25.31,27.27 U7.47 25.31,29.3 24.38,30.23 24.38,31.24 23.11,32.51 23.11,34.42 24,35.31 C84.P$2 | 25.78,27.05 26.04,27.05 26.31,27.33 U7.45 | C7.2 17.27,68.71 | C6.- 16.76,71.1 | C11.2 17.4,54.99 | C10.- 5.21,52.83 | C22.2 13.84,48.51 | C27.- | 6.48,48.51 C24.2 | U2.3 57.12,79.22 58.04,80.14 58.04,83.06 | U2.7 54.52,79.21 53.59,80.14 53.59,81.03 | U3.7 71.03,79.21 70.1,80.14 70.1,83.06 | U3.3 73.63,79.22 74.55,80.14 74.55,83.06 | U4.3 90.14,79.22 91.06,80.14 91.06,82.17 90.17,83.06 C53.2 88.9,83.06 | U4.7 87.54,79.21 86.61,80.14 86.61,83.06 | U14.4 108.71,60.71 | R101.2 107.19,67.69 | 113,67.69 C80.- | U13.7 39.24,60.83 40.26,59.82 40.51,59.82 | 40.51,59.82 41.78,59.82 | 41.78,59.82 43.05,59.82 | 43.05,59.82 44.32,59.82 | 44.32,59.82 45.59,59.82 | 45.59,59.82 46.74,59.82 47.62,60.71 C97.2 | 45.59,59.82 U13.13 | 44.32,59.82 U13.12 | 41.78,59.82 U13.10 | 40.51,58.93 U13.9 | 40.51,58.93 40.51,59.82 | 41.78,59.82 U13.5 | 43.05,59.82 U13.4 | 107.95,40.51 107.95,40.39 107.95,40.77 | 109.09,45.47 C40.2 | 85.09,52.7 C33.- | 83.82,49.15 C35.- 83.44,49.28 | R64.2 67.82,58.67 | 53.59,81.03 53.59,83.06 C50.2 55.88,83.06 | 55.88,83.06 C49.2 58.04,83.06 | 70.1,83.06 C52.2 72.39,83.06 | 72.39,83.06 C51.2 74.55,83.06 | 88.9,83.06 C54.2 86.61,83.06 | 55.88,87.25 55.88,83.06 | 72.39,83.06 72.39,87.25 | 88.9,83.06 88.9,87.25 | 70.68,51.88 70.74,51.94 | C67.- | U1.12 66.13,33.87 65.79,33.53 65.79,32.51 67.18,31.11 67.18,30.73 68.45,29.46 C13.2 | 71.63,37.21 71.69,37.27 | 71.63,41.15 71.65,41.17 | 71.63,38.61 71.66,38.57 | 93.73,42.55 93.79,42.48
  Top 0.254: 93.34,43.81 93.32,43.79 | 95.38,42.55 95.39,42.53 | 20.95,2.54 R63.1 20.57,1.91 20.19,1.52 14.99,1.52 GND.P$1 | 51.56,48.13 C15.2 | U1.74 56.27,40.52 56.01,40.26 54.99,40.26 54.55,40.7 51.56,40.7 | 70.03,47.45 70.1,47.37 | R27.2 46.86,75.31 46.86,72.52 R29.2 | C43.- | C45.- | C47.- 92.97,66.55 92.96,66.55 | C17.2 63.63,26.29 62.61,25.27 54.86,25.27 54.1,26.04 54.1,27.3 | 110.24,50.8 C41.- | 76.45,65.28 76.46,65.28 | C37.- | R26.2 48.01,79.76 49.28,81.03 53.59,81.03 | 27.3,21.25 U7.25 33.36,21.25 36.45,18.16 C94.P$2 | 27.3,21.25 27.3,21.21 27.31,21.2 U7.18 | 58.04,83.06 60.45,83.06 60.83,82.68 68.07,82.68 68.45,83.06 70.1,83.06 | 74.55,83.06 76.96,83.06 78.11,81.92 v80.64,81.92 83.82,81.92 84.96,83.06 86.61,83.06 | 45.09,27.56 U10.4 43.05,27.56 42.29,28.32 42.29,28.83 | C98.P$1 16.64,40.26 16.51,40.13 | C91.P$1 33.62,25.75 U7.34 28.8,25.75 v25.78,22.73 | 42.29,28.83 42.29,33.4 C96.P$2 | 42.29,28.83 U10.5 | v25.78,26.29 25.78,27.05 | 27.3,21.25 27.26,21.25 v25.78,22.73 | U7.9 25.76,22.75 v25.78,22.73 | C99.2 34.8,60.71 35.69,59.82 35.69,58.29 | 35.69,58.29 U11.2 | 102.87,88.52 J1.7 | 102.87,91.06 102.87,88.52 | 102.87,91.06 104.39,92.58 104.39,97.95 J1.1 | R92.2 99.31,82.3 100.33,83.31 100.33,85.98 99.82,86.49 99.82,87.88 100.46,88.52 102.87,88.52 | R41.1 90.17,93.98 88.9,95.25 J7.2 90.52,97.19 92.46,95.25 96.52,95.25 98.3,93.47 100.46,93.47 102.87,91.06 | C23.- | v14.35,28.57 | v14.35,28.57 | 59.94,44.45 59.92,44.42 | 70.68,48.9 70.74,48.9 70.82,48.97 | v66.17,36.58 66.13,36.53 | C12.2 55.5,31.37 55.37,31.37 54.1,30.1 54.1,27.3 | C29.- 4.04,88.42 | C30.2 33.53,55.12 34.54,56.13 37.72,56.13 38.23,56.64 38.23,58.29
  Top 0.254: 38.23,58.29 35.69,58.29 | 38.23,58.29 38.86,58.93 40.51,58.93 | v52.2,27.3 54.1,27.3
  Top 0.381: U1.2 59.63,34.1 59.37,33.85 57.59,33.85 56.77,33.02 C12.2 | 108.84,46.99 106.05,46.99 105.25,47.79 U5.18 102.58,47.79 101.73,48.64 101.73,50.16 102.55,50.99 U5.22 | 107.95,40.51 105.47,42.99 U5.12 101.92,42.99 101.47,42.55 95.38,42.55 93.73,42.55 93.34,42.93 93.34,43.81 93.34,45.09 93.04,45.39 U5.41 89.71,45.39 88.52,44.2 | C18.2 75.95,40.64 75.41,41.17 U1.28 | 93.79,42.48 U5.1 | 93.32,43.79 U5.43 | 95.39,42.53 U5.3 | 51.56,48.13 52.51,47.18 54.42,47.18 55.23,46.37 U1.65 59.04,46.37 59.94,45.47 59.94,44.45 59.94,41.78 v59.05,40.89 58.69,40.52 U1.74 | U5.34 90.87,50.99 90.42,51.44 | 59.92,44.42 U1.68
  Top 0.406: 70.68,51.88 U1.42 70.68,48.9 70.68,42.1 71.63,41.15 71.63,38.61 71.63,37.21 | C68.2 73.41,52.96 72.39,51.94 70.74,51.94 70.23,51.94 70.03,51.74 U1.43 70.03,47.45 | 71.63,37.21 71.63,36.7 71.33,36.4 U1.20 | 71.69,37.27 U1.22 | 71.65,41.17 U1.28 | 71.66,38.57 U1.24 | U1.53 63.53,48.23 64.39,47.37 69.98,47.37 | 70.1,47.37 69.98,47.37 | 70.82,48.97 U1.40 | 66.13,36.53 U1.12 | v70.61,37.21 71.63,37.21 | U1.2 59.63,37.53 59.05,38.1 v59.05,38.73 | 69.98,47.37 70.61,47.37
  Top 0.508: R43.1 v55.88,13.72 R45.1 54.1,13.21 54.1,6.99 | R93.2 C74.2 103.76,82.3 102.87,83.19 J1.7 | U8.5 5.02,31.44 4.7,31.11 C95.P$1 v3.56,29.72 | 109.47,60.71 R100.2 | C78.2 R101.2 | C78.2 113,67.69 | C16.2 51.56,40.7 C20.2 | 37.21,38.48 37.21,41.53 | 37.21,41.53 36.83,41.53 35.94,42.42 U12.7 35.03,44.6 33.53,46.1 C31.2 C30.2 | 37.21,41.53 38.48,41.53 | 38.48,41.53 39.75,41.53 | 38.48,41.53 U12.5 | 39.75,41.53 U12.11 | 42.29,41.53 U12.13 | 39.75,41.53 42.29,41.53 | 42.29,41.53 44.07,41.53 44.96,42.42 C32.2 47.12,42.42 v48.26,41.27 48.26,36.83 45.97,34.54 C96.P$2 | R96.2 v98.3,12.7 98.3,7.75 97.54,6.99 | J2.1 97.54,4.11 97.54,6.99 | C40.2 108.84,46.99 C42.2 110.24,49.66 110.24,50.8 | 85.09,52.7 86.23,53.85 90.42,53.85 | C38.2 93.22,59.44 C37.- 92.08,60.83 92.71,61.47 92.71,65.28 | C18.2 77.34,37.97 C14.2 | 20.95,2.54 24.38,2.54 | 24.38,2.54 U9.10 | C71.2 R91.1 | C46.2 76.45,68.2 C45.- | C48.2 92.96,68.2 C47.- | C68.2 73.66,56.26 71.25,58.67 C70.2 | C78.2 109.47,66.29 110.62,65.15 110.62,61.85 109.47,60.71 | C43.- 71.12,66.67 72.52,65.28 76.45,65.28 92.71,65.28 | 92.71,65.28 92.96,65.53 92.96,66.55 | 76.46,65.28 C45.- | 90.42,53.85 90.42,58.67 91.19,59.44 C37.- | 55.88,6.99 v64.14,6.99 70.61,6.99 | 70.61,6.99 72.39,6.99 | 72.39,6.99 v80.64,6.99 87.12,6.99 | 87.12,6.99 88.9,6.99 | 88.9,6.99 97.54,6.99 | 55.88,6.99 J4.2 | 72.39,6.99 J6.2 | 88.9,6.99 J8.2 | C41.- 110.11,52.32 105.92,56.52 105.92,60.2 106.43,60.71 U14.4 | 90.42,53.85 90.42,51.44 | U15.1 16,38.48 16.51,38.99 16.51,40.13 | J2.6 107.44,16.95 R95.2 | C67.- 81.91,53.47 82.68,52.7 C33.- | 24.38,2.54 26.04,0.89 44.07,0.89 50.16,6.99 54.1,6.99 | 54.1,6.99 55.88,6.99 | R49.1 70.61,13.21 70.61,6.99
  Top 0.508: R53.1 87.12,13.21 87.12,6.99 | C39.- 107.95,40.39 109.09,41.53 109.09,45.47 | 108.71,60.71 109.47,60.71 | C85.P$2 13.21,20.07 | USB.GND 9.47,21.26 10.16,20.57 | C91.P$1 34.54,26.67 34.54,30.86 37.21,33.53 37.21,38.48 | 37.21,38.48 U12.9 | LED9.C 124.84,6.86
  Top 0.61: U6.2 39.12,81.41 U6.7 | 39.12,80.14 U6.1 | 39.12,83.95 U6.4
  Top 0.762: C33.- 84.71,51.56 C34.2 86.11,49.15 | 86.11,49.15 C36.2 | 86.11,49.15 83.82,49.15 | C90.P$1 22.73,17.78 v22.35,17.4 | 86.11,44.2 88.52,44.2 | 86.11,44.2 R22.1 | 86.11,44.2 83.19,44.2 82.17,45.21 82.17,48.01 83.44,49.28
  Top 1.016: C89.P$2 v14.35,28.57 | C84.P$2 C83.P$2 23.5,37.59 22.61,38.48 22.61,42.55 21.34,43.81 16.51,43.81 | 39.12,81.03 39.12,81.41 39.12,83.95 39.12,85.85 | C71.2 40.01,79.12 39.12,80.01 39.12,81.03 | 40.01,79.38 40.01,81.03 39.12,81.03 | 39.12,81.03 39.12,80.14 | C44.2 59.94,68.2 C43.- | C98.P$1 v17.65,40.26 C92.P$1 | 16.51,43.81 C21.- | 16.51,43.81 16.51,40.13 | C82.- 14.23,28.7 v14.35,28.57 | 17.53,28.07 C88.P$2 | v19.05,26.29 C86.P$2 | C85.P$2 10.67,20.07 10.16,20.57 | v14.35,19.05 14.35,20.07 | 44.58,85.85 v44.58,84.33
  Top 1.27: R49.1 R47.1 | R53.1 R51.1 | R39.1 88.9,87.25 R41.1 | R35.1 72.39,87.25 R37.1 73.66,89.79 74.42,90.55 74.42,95.12 72.39,97.16 J5.2 | R31.1 55.88,87.25 R33.1 57.15,88.77 57.91,89.53 57.91,95.12 55.88,97.16 J3.2 | LED2.C LED1.C | LED3.C LED2.C | LED3.C LED4.C LED5.C | LED6.C LED5.C | LED7.C LED6.C | LED8.C LED7.C | LED9.C v124.84,8.26 LED8.C | 17.14,28.57 C89.P$2 | C88.P$2 17.27,28.45 | C4.- 17.65,76.7 C3.2 C1.2 18.29,80.26 17.14,81.41 17.14,86.36 | 17.55,75.33 C6.- 14.48,71.88 13.97,72.39 G1.- 11.18,72.39 5.21,66.42 C2.- 5.21,58.04 | 17.27,68.71 R5.1 | R129.1 C7.2 16.76,71.1 | 17.4,54.99 R7.1 | 15.37,58.04 C5.- | 5.21,52.83 5.21,58.04 | C8.2 17.93,47.9 C9.- 15.49,46.1 | C26.2 15.37,96.01 C25.- C27.- | C27.- 15.37,88.78 C28.2 14.86,86.36 | R26.2 R27.2 | C68.2 C69.2 77.72,52.96 C67.- | C70.2 R64.2 C19.2 | J1.1 109.67,99.62 111.51,97.79 MIC.P- 117.47,93.34 117.47,88.27 117.98,87.76 CON1.3 | 5.21,58.04 15.37,58.04 | C11.2 16.89,56.52 15.37,58.04 | v102.87,21.21 C77.2 | v27.43,99.31 SW3.P$2 25.02,100.33 11.56,100.33 v10.16,98.93 | C29.- 4.19,88.27 v5.08,87.38 6.1,86.36 v10.16,86.36 14.86,86.36 | 17.14,86.36 14.86,86.36 | R3.1 17.91,87.12 17.14,86.36 | C10.- 4.83,52.48 4.83,48.51 | 5.49,43.91 4.83,43.91 4.83,48.51 | 5.49,43.91 C23.- | C21.- 15.49,44.57 15.49,46.1 | 15.49,46.1 15.49,47.62 14.61,48.51 C22.2 | 5.49,43.91 5.49,43.41 6.73,42.16 13.46,42.16 14.73,43.44 C21.- | C21.- | 4.83,48.51 6.48,48.51 | 13.21,20.07 C93.1 | C86.P$2 17.53,28.07 | C85.P$2 14.35,20.07 15.37,20.07 C87.P$2 | v1.14,6.22 R8.1 | R68.2 39.12,85.85 R67.2 R66.2 44.58,85.85 R65.2
  Bottom 0.254: 55.88,97.16 J3.2
  Bottom 0.762: 103,12.7 103,9.4 104.39,8 106.93,8 109.22,5.71 121.28,5.71 123.83,8.26 v124.84,8.26
  Bottom 1.016: v25.78,22.73 v25.78,26.29 v19.05,26.29 18.41,26.29 12.83,20.7 12.83,19.05 | GND.P$1 13.97,12.7 12.83,13.84 12.83,19.05 | J2.6 103.19,12.7 103,12.7 v98.3,12.7 98.3,14.35 102.87,18.92 v102.87,21.21 | v14.35,28.57 4.7,28.57 v3.56,29.72 | v70.61,37.21 69.98,36.58 v66.17,36.58 64.52,34.92 62.23,34.92 59.05,38.1 v59.05,38.73 v59.05,40.89 | v55.88,13.72 55.88,20.83 52.2,24.51 v52.2,27.3 | v27.43,99.31 29.84,96.9 47.24,96.9 48.77,95.38 54.1,95.38 55.88,97.16 | 12.83,19.05 v14.35,19.05 16,17.4 v22.35,17.4 | v117.98,56.52 119.76,58.29
  Bottom 1.27: CON1.26 CON1.25 119.76,58.29 | v10.16,86.36 v10.16,98.93 | v1.14,6.22 5.71,6.22 9.4,2.54 GND.P$1
  other vias: 88.14,65.28 82.55,62.87 82.55,67.31 74.93,64.14 45.09,1.91 47.12,13.34 52.7,18.41 58.42,18.41 97.16,10.79 109.22,3.81 97.16,24.77 104.14,24.77 29.97,25.78 17.14,57.78 8.89,56.52 3.81,76.2 13.34,86.36 64.14,94.61 80.64,94.61 97.16,92.08 114.94,53.98 111.12,53.98 102.87,37.47 107.31,37.47 48.26,34.29 46.99,49.53 40.64,59.69 46.99,59.05 64.14,67.31 114.3,82.55 0.89,17.02 86.36,75.56 104.14,76.83 103.5,71.75 80.64,55.88 70.48,41.91 62.23,41.91 70.48,46.99 83.82,39.75 59.05,48.9 62.87,48.9 37.47,41.27 40.01,50.16 1.52,29.72 2.54,43.81 5.08,50.16 15.49,45.72 64.14,81.53 28.07,35.31 60.33,77.72 52.58,75.06 34.16,15.62 28.83,8.13 39.37,18.03
  pour Top (isolate 0.254, rank 6): -10.16,104.14 132.08,104.14 132.08,-8.89 -10.16,-8.89
  pour Bottom (isolate 0.254, rank 6): -5.08,104.14 132.08,104.14 132.08,-7.62 -5.08,-7.62
GPLED0  (via drill 0.6)
  Top 0.254: U1.11 65.48,33.98 65.28,33.78 65.28,32.26 66.55,30.99 66.55,30.61 66.93,30.23 66.93,28.83 67.69,28.07 73.03,28.07 75.56,30.61 111.89,30.61 v115.19,27.3
  Top 1.016: v115.19,27.3 R9.2
  Bottom 0.254: v115.19,27.3 119,31.11 119,51.69 115.57,55.12 115.57,75.95 CON1.9
GPLED1  (via drill 0.6)
  Top 0.254: v72.39,27.18 72.9,27.18 75.82,30.1 111.38,30.1 114.3,27.18 114.3,25.65 v115.19,24.77
  Top 0.381: U1.9 64.18,31.33 v64.52,30.99
  Top 1.016: v115.19,24.77 R10.2
  Bottom 0.254: v64.52,30.99 67.44,28.07 71.5,28.07 v72.39,27.18 | v115.19,24.77 119.51,29.08 119.51,51.94 116.08,55.37 116.08,73.91 CON1.11
GPLED2  (via drill 0.6)
  Top 0.254: v75.69,28.7 76.58,29.59 111.12,29.59 113.79,26.92 113.79,23.62 v115.19,22.23
  Top 0.406: U1.21 72.64,36.62 72.64,36.24
  Top 1.016: v115.19,22.23 R11.2 | v72.64,35.81 72.64,36.24
  Bottom 0.254: v72.64,35.81 73.53,34.92 75.44,34.92 76.45,33.91 76.45,29.46 v75.69,28.7 | v115.19,22.23 120.02,27.05 120.02,52.2 116.59,55.63 116.59,71.88 CON1.13
GPLED3  (via drill 0.6)
  Top 0.254: v76.96,28.7 77.22,28.96 111,28.96 113.28,26.67 113.28,21.59 v115.19,19.68
  Top 0.381: U1.23 73.96,37.92 74.17,37.72 v74.17,35.81
  Top 1.016: v115.19,19.68 R12.2
  Bottom 0.254: v76.96,28.7 76.96,34.16 75.31,35.81 v74.17,35.81 | v115.19,19.68 120.52,25.02 120.52,52.45 117.09,55.88 117.09,69.85 CON1.15
GPLED4  (via drill 0.6)
  Top 0.254: v76.83,27.43 77.34,27.43 78.36,28.45 110.74,28.45 112.78,26.42 112.78,19.56 v115.19,17.14
  Top 0.381: U1.26 74.3,39.87 v74.93,39.24
  Top 1.016: v115.19,17.14 R13.2
  Bottom 0.254: v76.83,27.43 77.34,27.43 77.85,27.94 77.85,36.32 v74.93,39.24 | CON1.16 123.57,71.25 123.57,55.24 121.03,52.7 121.03,22.99 v115.19,17.14
GPLED5  (via drill 0.6)
  Top 0.254: v75.56,27.43 76.45,26.54 77.22,26.54 78.61,27.94 110.49,27.94 112.27,26.16 112.27,17.53 v115.19,14.61
  Top 0.381: U1.27 75.17,40.52 76.2,39.5 v76.2,39.24
  Top 1.016: v115.19,14.61 R14.2
  Bottom 0.254: v75.56,27.43 76.45,26.54 77.22,26.54 78.36,27.69 78.36,37.08 v76.2,39.24 | CON1.14 124.21,73.15 124.21,55.12 121.54,52.45 121.54,20.95 v115.19,14.61
GPLED6  (via drill 0.6)
  Top 0.254: v71.12,27.18 72.26,26.04 77.47,26.04 78.87,27.43 110.24,27.43 111.76,25.91 111.76,15.49 v115.19,12.06 | U1.72 56.22,41.82 56.01,42.04 v54.74,42.04
  Top 1.016: v115.19,12.06 R15.2
  Bottom 0.254: v71.12,27.18 69.72,25.78 66.67,25.78 57.4,35.05 55.5,35.05 54.74,35.81 v54.74,42.04 | CON1.12 124.71,75.18 124.71,54.74 122.05,52.07 122.05,18.92 v115.19,12.06
GPLED7  (via drill 0.6)
  Top 0.254: U1.73 55.65,41.17 v55.63,41.15 | v69.85,27.18 71.5,25.53 77.72,25.53 79.12,26.92 109.98,26.92 111.25,25.65 111.25,13.46 v115.19,9.53
  Top 1.016: v115.19,9.53 R16.2
  Bottom 0.254: v69.85,27.18 68.96,26.29 66.93,26.29 57.66,35.56 55.75,35.56 55.24,36.07 55.24,39.88 55.63,40.26 v55.63,41.15 | CON1.10 125.22,77.22 125.22,54.48 122.56,51.82 122.56,16.89 v115.19,9.53
GPLED8  (via drill 0.6)
  Top 0.254: v68.58,27.18 70.74,25.02 77.98,25.02 79.38,26.42 109.73,26.42 110.74,25.4 110.74,11.43 v115.19,6.99
  Top 0.406: U1.80 56.31,36.62 v56.13,36.45
  Top 1.016: v115.19,6.99 R17.2
  Bottom 0.254: v68.58,27.18 66.8,27.18 57.53,36.45 v56.13,36.45 | CON1.8 125.73,79.25 125.73,54.23 123.06,51.56 123.06,14.86 v115.19,6.99
GPSW0
  Top 0.254: CON1.17 117.47,67.69 117.47,58.55 118.87,57.15 118.87,52.32 118.24,51.69 113.92,51.69 112.9,50.67 R76.2 109.86,47.37 109.86,40.64 109.09,39.88 109.09,36.45 107.57,34.92 72.77,34.92 71.75,33.91 70.87,33.91 70.68,34.1 U1.19
GPSW1
  Top 0.254: CON1.19 117.98,65.66 117.98,58.8 119.38,57.4 119.38,50.16 118.36,49.15 113.92,49.15 112.9,48.13 R75.2 110.62,45.59 110.62,40.64 109.6,39.62 109.6,36.2 107.82,34.42 73.03,34.42 72.01,33.4 70.61,33.4 70.03,33.99 U1.18
GPSW2  (via drill 0.6)
  Top 0.254: 112.9,45.59 113.92,46.61 118.36,46.61 119.89,48.13 119.89,57.66 118.49,59.05 118.49,63.63 CON1.21 | v73.28,33.4 73.79,33.91 108.08,33.91 110.11,35.94 110.11,39.37 111.12,40.39 111.12,43.56 R74.2
  Top 0.381: U1.13 66.78,32.99 v66.67,32.89
  Top 0.406: R74.2 112.9,45.59
  Bottom 0.254: v66.67,32.89 67.18,33.4 v73.28,33.4
GPSW3  (via drill 0.6)
  Top 0.254: 112.9,43.05 113.92,44.07 118.49,44.07 120.52,46.1 120.52,53.85 121.03,54.36 121.03,61.09 CON1.23 | v70.61,32.51 73.66,32.51 74.55,33.4 108.33,33.4 110.62,35.69 110.62,39.12 111.63,40.13 111.63,41.53 R73.2 | U1.14 67.43,33.54 67.82,33.15 v67.82,32.38
  Top 0.406: R73.2 112.9,43.05
  Bottom 0.254: v70.61,32.51 68.71,32.51 68.58,32.38 v67.82,32.38
GPSW4  (via drill 0.6)
  Top 0.254: 112.9,40.51 113.92,41.53 118.49,41.53 121.03,44.07 121.03,53.59 123.7,56.26 123.7,60.96 CON1.24 | v71.63,31.62 73.53,31.62 74.8,32.89 108.71,32.89 111.12,35.31 111.12,38.48 R72.2 | U1.15 68.08,33.65 68.71,33.02 68.71,31.75 v68.07,31.11
  Top 0.406: R72.2 112.9,40.51
  Bottom 0.254: v71.63,31.62 70.1,31.62 69.85,31.88 68.83,31.88 v68.07,31.11
GPSW5  (via drill 0.6)
  Top 0.254: CON1.22 124.21,62.99 124.21,55.88 121.79,53.47 121.79,42.29 118.49,38.99 113.92,38.99 112.9,37.97 | v72.64,30.73 73.41,30.73 75.06,32.38 108.97,32.38 111.63,35.05 111.63,36.45 R71.2 | v69.34,30.99 69.22,31.11 69.22,33.27 68.73,33.76 U1.16
  Top 0.406: R71.2 112.9,37.97
  Bottom 0.254: v72.64,30.73 70.87,30.73 70.61,30.99 v69.34,30.99
GPSW6  (via drill 0.6)
  Top 0.254: CON1.20 124.71,65.02 124.71,55.63 122.43,53.34 122.43,40.39 118.49,36.45 113.92,36.45 112.9,35.43 | U1.70 55.81,43.12 55.12,43.81 v54.74,43.81 | v71.63,29.84 73.28,29.84 75.31,31.88 109.6,31.88 R70.2
  Top 0.406: R70.2 112.9,35.43
  Bottom 0.254: v54.74,43.81 55.12,43.81 57.15,41.78 57.15,38.35 63.12,32.38 65.15,32.38 67.69,29.84 v71.63,29.84
GPSW7  (via drill 0.6)
  Top 0.254: 112.9,32.89 113.92,33.91 118.49,33.91 123.06,38.48 123.06,53.09 125.22,55.24 125.22,67.06 CON1.18 | U1.69 56.43,43.77 v55.88,44.32 | v72.64,28.96 73.15,28.96 75.56,31.37 111.63,31.37 R69.2
  Top 0.406: R69.2 112.9,32.89
  Bottom 0.254: v72.64,28.96 67.82,28.96 64.9,31.88 62.87,31.88 56.64,38.1 56.64,41.4 55.12,42.93 54.23,42.93 53.85,43.31 53.85,44.2 54.36,44.7 55.5,44.7 v55.88,44.32
HREQ  (via drill 0.6)
  Top 0.254: R140.1 20.19,18.29 22.1,18.29 23.11,19.3 v24,19.3 24.38,19.68 24.8,19.68 U7.13 | v86.87,25.53 86.87,24.26 82.93,20.32 50.8,20.32 43.69,13.21 v43.69,8.89
  Top 0.381: U1.38 74.72,47.67 v75.31,48.26
  Bottom 0.254: v75.31,48.26 76.71,48.26 77.22,48.77 80.52,48.77 81.92,47.37 81.92,44.07 82.93,43.05 82.93,29.97 86.87,26.04 v86.87,25.53 | v24,19.3 24,17.53 22.99,16.51 20.57,16.51 20.07,16 20.07,10.16 23.24,6.99 39.75,6.99 41.15,8.38 43.18,8.38 v43.69,8.89
IN_0_L  (via drill 0.6)
  Top 0.254: 96.52,78.74 C72.+
  Top 0.381: v97.66,62.74 97.54,62.87 97.54,77.72 96.52,78.74 | U5.38 93.64,47.79 93.85,48.01 v94.61,48.01
  Bottom 0.381: v94.61,48.01 95.12,48.01 101.85,54.74 101.85,60.71 99.82,62.74 v97.66,62.74
IN_0_R  (via drill 0.6)
  Top 0.381: C73.+ 100.58,79.75 99.57,78.74 99.57,61.47 v100.33,60.71 | U5.37 93.42,48.59 v93.98,49.15
  Bottom 0.381: v93.98,49.15 95.25,49.15 101.22,55.12 101.22,59.82 v100.33,60.71
IN_0_SPDIF  (via drill 0.6)
  Top 0.381: U5.42 90.31,44.59 v90.04,44.32 | v98.55,63.88 98.55,78.99 100.46,80.9 101.22,80.9 101.6,81.28 R94.1
  Bottom 0.381: v98.55,63.88 99.57,63.88 102.62,60.83 102.62,54.23 92.71,44.32 v90.04,44.32
IN_1_L  (via drill 0.6)
  Top 0.254: U2.2 57.77,79.11 58.55,79.88 58.55,81.92 58.8,82.17 v59.44,82.17
  Top 0.508: v62.61,83.69 C56.+
  Bottom 0.508: v59.44,82.17 60.96,83.69 v62.61,83.69
IN_1_R  (via drill 0.6)
  Top 0.254: U2.1 58.42,79 59.44,80.01 v59.44,80.9
  Top 0.508: v51.69,83.69 50.16,83.69 49.78,84.07 C55.+
  Bottom 0.508: v59.44,80.9 59.05,80.9 56.26,83.69 v51.69,83.69
IN_2_L  (via drill 0.6)
  Top 0.254: U3.2 74.28,79.11 75.06,79.88 75.06,81.92 75.31,82.17 v75.95,82.17 | 79.25,85.21 C58.+
  Top 0.508: v79.25,83.69 79.25,85.21
  Bottom 0.508: v75.95,82.17 77.47,83.69 v79.25,83.69
IN_2_R  (via drill 0.6)
  Top 0.254: U3.1 74.93,79 75.95,80.01 v75.95,80.9
  Top 0.508: v65.66,83.69 C57.+
  Bottom 0.508: v65.66,83.69 72.14,83.69 72.52,83.69 75.31,80.9 v75.95,80.9
IN_3_L
  Top 0.254: U4.2 90.79,79.11 91.57,79.88 91.57,81.41 91.57,82.42 93.6,84.45 95.25,84.45 95.63,84.84 C60.+
IN_3_R  (via drill 0.6)
  Top 0.254: U4.1 91.44,79 92.46,80.01 v92.46,80.9
  Top 0.508: v82.17,83.69 C59.+
  Bottom 0.508: v92.46,80.9 89.66,83.69 v82.17,83.69
JTAG/ONCE  (via drill 0.6)
  Top 0.254: LED10.C 6.86,13.97 7.87,14.99 20.7,14.99 21.21,15.49 v21.21,15.62 | v25.53,15.62 26.04,15.62 26.92,16.51 27.56,16.51 27.81,16.76 U7.19 | 22.73,13.97 U9.1
  Top 0.508: R133.1 4.45,13.34 6.86,13.34 LED10.C | 22.73,13.97 21.84,13.08 v21.59,13.08
  Bottom 0.254: v21.21,15.62 22.86,15.62 23.24,16 24.51,16 24.89,15.62 v25.53,15.62
  Bottom 0.508: v21.59,13.08 21.21,13.46 v21.21,15.62
LRCLK  (via drill 0.6)
  Top 0.254: U4.14 87.54,70.91 86.87,70.23 84.84,70.23 80.39,74.68 72.39,74.68 71.03,73.32 U3.14 71.03,70.91 70.36,70.23 68.33,70.23 63.88,74.68 55.88,74.68 54.52,73.32 U2.14 54.48,71.89 54.48,70.36 54.36,70.23 54.36,64.39 54.99,63.75 54.99,63.25 52.83,61.09 52.32,61.09 51.56,60.33 R83.2 51.31,58.67 50.42,57.78 50.42,55.63 R84.2 49.4,52.32 49.4,47.12 48.9,46.61 48.9,43.18 49.78,42.29 49.78,38.48 50.55,37.72 50.55,34.42 R60.1
  Top 0.356: U4.14 87.54,73.57 89.03,75.06 93.73,75.06 96.65,72.14 96.65,62.23 97.16,61.72 v98.55,61.72
  Top 0.508: R61.1 R60.1 | v96.65,59.44 R23.2
  Bottom 0.508: v96.65,59.44 98.55,61.34 v98.55,61.72
MCKO1
  Top 0.254: U2.15 55.17,73.21 56.13,74.17 63.63,74.17 68.07,69.72 70.61,69.72 71.68,70.8 U3.15 71.68,73.21 72.64,74.17 80.14,74.17 84.58,69.72 87.12,69.72 88.19,70.8 U4.15 | 101.22,58.55 R25.2
  Top 0.356: U4.15 88.19,73.33 89.28,74.42 93.47,74.42 96.01,71.88 96.01,61.85 96.77,61.09 97.66,61.09 100.2,58.55 101.22,58.55
MISO/SDA  (via drill 0.6)
  Top 0.254: U1.35 76.2,45.72 77.09,46.61 78.11,46.61 v78.49,46.99 | v82.04,25.53 82.04,24.51 80.39,22.86 49.53,22.86 40.77,14.1 v40.77,11.05 40.77,7.62 39.75,6.6 39.75,3.68 R124.P$2 | R117.P$2 47.37,30.48 | v42.29,25.4 43.31,24.38 47.75,24.38 49.28,25.91 R116.P$2 | v43.81,74.17 42.93,73.28 42.93,70.48 46.48,66.93 v46.48,65.28
  Top 0.508: R117.P$2 48.77,30.35 49.28,29.84 R111.2 R116.P$2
